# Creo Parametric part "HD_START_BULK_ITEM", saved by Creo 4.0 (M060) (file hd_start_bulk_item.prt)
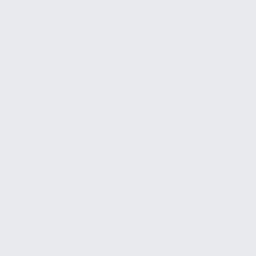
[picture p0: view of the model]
Units: Inch lbm Second (Pro/E Default); INCH, POUND, SECS

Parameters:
  REFERENCE = "BULK"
